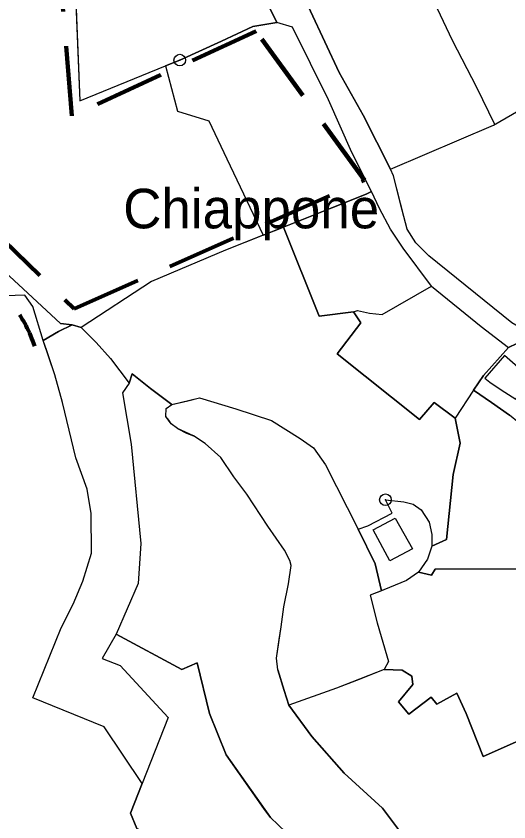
# Model space of a CAD drawing. Extents: x 645880 to 658994, y 884400 to 894744.
# Drawn here: x 657636.1 to 657847.7, y 891569 to 891915 of the extents above; entities that cross this region are included whole.
import ezdxf
from ezdxf.enums import TextEntityAlignment as Align

# ---------------------------------------------------------------- set-up
doc = ezdxf.new("R2010")
doc.units = 0
doc.header["$LTSCALE"] = 10
doc.header["$PDMODE"] = 32
doc.header["$PDSIZE"] = 5
doc.linetypes.add('MEDIUM_DASHED', pattern=[4.5, 3, -1.5])
doc.linetypes.add('SHORT_DASHED', pattern=[2.7, 1.5, -1.2])
for name, color, linetype, lineweight in [('1', 7, 'Continuous', 25), ('13', 7, 'Continuous', 25), ('15', 7, 'MEDIUM_DASHED', 100), ('26', 7, 'Continuous', 25), ('32', 7, 'Continuous', 25), ('41', 7, 'Continuous', 40), ('55', 7, 'Continuous', 25), ('8', 7, 'Continuous', 25), ('9', 7, 'Continuous', 25)]:
    doc.layers.add(name, color=color, linetype=linetype, lineweight=lineweight)
doc.layers.add('60', color=7, linetype='Continuous')

msp = doc.modelspace()

# ---------------------------------------------------------------- linework, layer by layer
at = {"layer": '1'}
for points in [[(657869.29, 891769.47), (657862, 891775.28), (657858.28, 891777.83), (657847.5, 891772.66)], [(657847.5, 891772.66), (657836.84, 891760.76), (657832.51, 891754.43), (657840.28, 891749.06), (657848.05, 891743.69)], [(657782.96, 891694.68), (657787.2, 891696.06), (657797.54, 891701.6), (657794.71, 891707.33)], [(657802.54, 891706.38), (657806.57, 891705.45), (657810.06, 891703.01), (657813.53, 891697.74), (657814.62, 891692.45), (657814.58, 891687.36), (657812.8, 891681.77), (657808.92, 891676.2), (657803.69, 891672.63), (657794.06, 891668.59), (657792.94, 891668.23), (657790.32, 891679.88), (657782.96, 891694.68)]]:
    msp.add_lwpolyline(points, dxfattribs=at)
for points in [[(657867.89, 891752.17), (657853.82, 891762.29), (657845.89, 891769.33), (657837.33, 891759.6), (657839.49, 891757.8), (657844.41, 891754.59), (657850.75, 891750.51), (657853.31, 891753.71), (657863.41, 891746.41)], [(657789.44, 891694.38), (657798.88, 891699.44), (657806.26, 891686.22), (657796.54, 891681.08)]]:
    msp.add_lwpolyline(points, close=True, dxfattribs=at)
msp.add_point((657794.71, 891707.33), dxfattribs=at)
at = {"layer": '13'}
for points in [[(657432.76, 891843.52), (657469.74, 891871.41), (657496.82, 891788.11), (657619.04, 891816.35), (657655.09, 891783.05)], [(657655.09, 891783.05), (657660.19, 891782.51), (657654.33, 891779.66), (657647.73, 891775.77), (657643.28, 891790.37), (657639.86, 891795.15), (657627.13, 891794.74)], [(657709.8, 891749.85), (657714.86, 891751.08), (657730.44, 891746.35), (657745.75, 891741.38)], [(657709.27, 891735.99), (657705.39, 891737.91), (657702.65, 891739.93), (657701.65, 891741.44), (657700.38, 891743.11), (657700.58, 891746.53), (657702.97, 891748.19), (657709.8, 891749.85)], [(657745.75, 891741.38), (657758.07, 891733.66), (657763.76, 891729.58), (657768.91, 891722.35), (657782.96, 891694.68), (657790.32, 891679.88), (657792.94, 891668.23), (657788.18, 891666.42), (657791.15, 891654.44), (657792.82, 891648.53), (657795.99, 891637.83), (657794.21, 891634.37), (657782.32, 891629.77), (657773.68, 891626.41), (657753.26, 891619.18)], [(657749.11, 891647.27), (657749.93, 891652.71), (657751.03, 891661.3), (657753.09, 891671.25), (657754.23, 891679.11), (657753.65, 891681.17), (657751.36, 891685.75), (657744.12, 891696.02), (657735.2, 891709.72), (657729.59, 891717.12), (657724.05, 891725.43), (657717.28, 891731.51), (657712.28, 891734.73), (657709.27, 891735.99)], [(657678.98, 891649.67), (657673.01, 891639.13), (657680.69, 891636.19), (657701.38, 891613.82), (657690.25, 891585.42)], [(657678.98, 891649.67), (657673.01, 891639.13), (657680.69, 891636.19), (657701.38, 891613.82), (657690.25, 891585.42), (657685.19, 891572.75), (657687.9, 891566.1), (657729.26, 891544.2), (657738.1, 891535.49)], [(657713.85, 891637.29), (657707.19, 891634.42), (657678.98, 891649.67)], [(657753.26, 891619.18), (657751.27, 891625.38), (657748.45, 891634.33), (657747.88, 891639.32), (657749.11, 891647.27)], [(657782.7, 891539.42), (657765.1, 891551.91), (657745.3, 891570.84), (657742.5, 891574.78), (657726.25, 891597.71), (657719.17, 891615.54), (657713.85, 891637.29)]]:
    msp.add_lwpolyline(points, dxfattribs=at)
at = {"layer": '15'}
msp.add_lwpolyline([(657323.77, 891717.8), (657394.25, 891834.07), (657474.26, 891879.81), (657500.92, 891799.76), (657624.74, 891824.54), (657660.93, 891789.28), (657785.69, 891844.55), (657739.13, 891908.57), (657659.98, 891872.19), (657653.31, 891953.19)], dxfattribs=at)
at = {"layer": '26'}
msp.add_line((657796.81, 891849.31), (657841.15, 891868.23), dxfattribs=at)
for points in [[(657758.69, 892137.73), (657757.11, 892135.65), (657749.33, 892122.75), (657744.59, 892112.88), (657742.31, 892105.2), (657741.36, 892090.31), (657742.18, 892050.76), (657743.37, 891989.94), (657744.93, 891965.34), (657750.21, 891944.26), (657762.46, 891917.16), (657774.87, 891890.81), (657785.16, 891872.46), (657796.81, 891849.31)], [(657841.15, 891868.23), (657881.18, 891891.34), (657903.67, 891854.63), (657911.35, 891843.44), (657994.66, 891890.15), (657997.88, 891892.48)]]:
    msp.add_lwpolyline(points, dxfattribs=at)
at = {"layer": '32'}
for points in [[(657660.06, 891962.27), (657663.45, 891878.6), (657700.24, 891893.63)], [(657742.24, 891820.98), (657726, 891814.54), (657694.16, 891801), (657664.05, 891781.35), (657660.19, 891782.51), (657655.09, 891783.05), (657619.04, 891816.35), (657496.82, 891788.11), (657496.82, 891788.11), (657469.74, 891871.41), (657432.76, 891843.52), (657429.08, 891844.98), (657422.3, 891845.12), (657414.96, 891840.81), (657410.91, 891832.97), (657412.56, 891823.6), (657398.01, 891831.07), (657351.25, 891848.9), (657334.55, 891854.45), (657336.53, 891898.64), (657333.31, 891925.98)], [(657748.04, 891912.29), (657737.78, 891910.62), (657724.24, 891904.23), (657706.38, 891896.14), (657700.24, 891893.63)], [(657788.68, 891839.73), (657780.33, 891856.49), (657770.21, 891879.15), (657754.85, 891910.24), (657748.04, 891912.29)], [(657700.24, 891893.63), (657705.45, 891874.29), (657718.91, 891870), (657726.64, 891853.82)], [(657700.24, 891893.63), (657705.45, 891874.29), (657718.91, 891870), (657726.64, 891853.82), (657742.24, 891820.98)], [(657848.94, 891783.31), (657813.3, 891812.14), (657807.8, 891817.64), (657804.01, 891823.52), (657801.92, 891831.68), (657798.13, 891846.47), (657796.81, 891849.31), (657841.15, 891868.23), (657881.18, 891891.34)], [(657726.64, 891853.82), (657742.24, 891820.98), (657786.43, 891838.51), (657788.68, 891839.73)]]:
    msp.add_lwpolyline(points, dxfattribs=at)
at = {"layer": '41', "linetype": 'SHORT_DASHED', "lineweight": 80}
msp.add_arc((657590.77, 891756.16), 55.95, 17.7593, 57.1028, dxfattribs=at)
at = {"layer": '55'}
for points in [[(657841.64, 891868.51), (657833.93, 891884.34), (657823.46, 891904.64), (657804.01, 891945.77), (657799.28, 891957.09), (657796.41, 891967.76), (657795.72, 891971.23), (657794.89, 891982.35), (657792.85, 892070.98), (657792.65, 892093.07), (657794.14, 892096.06), (657804.02, 892113.46), (657812.57, 892128.28), (657814.84, 892148), (657816.57, 892152.85), (657808.89, 892139.52)], [(657735.78, 892010.9), (657735.34, 891976.8), (657736.37, 891963.27), (657738.03, 891948.21), (657743.89, 891923.77), (657745.11, 891918.4), (657748.04, 891912.29)], [(657744.93, 891965.34), (657750.21, 891944.26), (657762.46, 891917.16), (657774.87, 891890.81), (657785.16, 891872.46), (657796.81, 891849.31), (657841.15, 891868.23), (657841.64, 891868.51)], [(657796.81, 891849.31), (657785.16, 891872.46), (657774.87, 891890.81), (657762.46, 891917.16), (657750.21, 891944.26), (657744.93, 891965.34)], [(657748.04, 891912.29), (657737.78, 891910.62), (657724.24, 891904.23), (657706.38, 891896.14), (657700.24, 891893.63)], [(657700.24, 891893.63), (657705.45, 891874.29), (657718.91, 891870), (657726.64, 891853.82), (657742.24, 891820.98), (657750.85, 891824.4), (657766.25, 891786.18), (657781.02, 891788.05), (657784.13, 891783.26), (657773.99, 891769.98), (657809.36, 891741.8), (657815.59, 891749.14), (657824.59, 891742.44), (657826.73, 891731.58), (657823.82, 891718.16), (657820.92, 891690.19), (657814.58, 891687.36), (657812.8, 891681.77), (657808.92, 891676.2), (657803.69, 891672.63), (657794.06, 891668.59), (657788.18, 891666.42), (657791.15, 891654.44), (657792.82, 891648.53), (657795.99, 891637.83), (657794.21, 891634.37), (657773.68, 891626.41), (657753.26, 891619.18), (657763.03, 891605.7), (657777.02, 891589.95), (657793.46, 891574.89), (657807.15, 891556.57)], [(657832.51, 891754.43), (657836.84, 891760.76), (657847.5, 891772.66), (657858.28, 891777.83), (657848.94, 891783.31), (657813.3, 891812.14), (657807.8, 891817.64), (657804.01, 891823.52), (657798.13, 891846.47), (657796.81, 891849.31)], [(657859.76, 891733.14), (657855.89, 891736.52), (657851.89, 891740.44), (657848.05, 891743.69), (657840.28, 891749.06), (657832.51, 891754.43)]]:
    msp.add_lwpolyline(points, dxfattribs=at)
at = {"layer": '8'}
msp.add_line((657706.38, 891896.14), (657724.24, 891904.23), dxfattribs=at)
for points in [[(657736.37, 891963.27), (657723.99, 891959.82), (657704.2, 891955.52), (657679.94, 891949.67), (657667.55, 891947.95), (657660.68, 891946.99), (657663.45, 891878.6)], [(657748.04, 891912.29), (657745.11, 891918.4), (657743.89, 891923.77), (657738.03, 891948.21), (657736.37, 891963.27)], [(657724.24, 891904.23), (657737.78, 891910.62), (657748.04, 891912.29)], [(657663.45, 891878.6), (657700.24, 891893.63), (657706.38, 891896.14)], [(657781.02, 891788.05), (657782.65, 891788.55), (657787.88, 891787.41), (657793.25, 891786.87), (657814.44, 891799.12), (657802.35, 891815.38), (657796.87, 891823.5), (657792.15, 891832.39), (657788.68, 891839.73), (657786.43, 891838.51), (657750.85, 891824.4)], [(657750.85, 891824.4), (657726, 891814.54), (657694.16, 891801), (657664.05, 891781.35), (657670.38, 891774.88), (657676.65, 891768.05), (657684.63, 891757.38), (657685.98, 891761.42), (657693.74, 891755.08), (657702.97, 891748.19), (657714.86, 891751.08), (657730.44, 891746.35), (657745.75, 891741.38), (657758.07, 891733.66), (657763.76, 891729.58), (657768.91, 891722.35), (657782.96, 891694.68), (657787.2, 891696.06), (657797.54, 891701.6), (657794.71, 891707.33), (657802.54, 891706.38), (657806.57, 891705.45), (657810.06, 891703.01), (657813.53, 891697.74)], [(657750.85, 891824.4), (657766.25, 891786.18), (657781.02, 891788.05)], [(657781.02, 891788.05), (657766.25, 891786.18), (657750.85, 891824.4)], [(657652.64, 891760.91), (657647.73, 891775.77), (657643.28, 891790.37), (657639.86, 891795.15), (657627.13, 891794.74)], [(657824.59, 891742.44), (657815.59, 891749.14), (657809.36, 891741.8), (657773.99, 891769.98), (657784.13, 891783.26), (657781.02, 891788.05)], [(657664.76, 891672.32), (657668.49, 891684.45), (657668.36, 891701.4), (657666.65, 891711.82), (657661.77, 891725.35), (657656.05, 891749.04), (657652.64, 891760.91), (657649.27, 891771.3), (657647.73, 891775.77), (657654.33, 891779.66), (657660.19, 891782.51), (657664.05, 891781.35)], [(657664.05, 891781.35), (657670.38, 891774.88), (657676.65, 891768.05), (657684.63, 891757.38), (657681.69, 891753.19)], [(657685.98, 891761.42), (657684.63, 891757.38), (657681.69, 891753.19), (657685.45, 891731.19)], [(657700.38, 891743.11), (657700.58, 891746.53), (657702.97, 891748.19), (657693.74, 891755.08), (657685.98, 891761.42)], [(657661.77, 891725.35), (657656.05, 891749.04), (657652.64, 891760.91)], [(657859.76, 891733.14), (657855.89, 891736.52), (657851.89, 891740.44), (657848.05, 891743.69), (657840.28, 891749.06), (657832.51, 891754.43), (657824.59, 891742.44)], [(657681.69, 891753.19), (657685.45, 891731.19), (657689.68, 891688.51), (657689.68, 891688.51), (657689.68, 891688.5), (657689.69, 891688.5), (657688.53, 891671.33), (657678.98, 891649.67)], [(657709.27, 891735.99), (657705.39, 891737.91), (657702.65, 891739.93), (657700.38, 891743.11)], [(657824.59, 891742.44), (657826.73, 891731.58), (657823.82, 891718.16), (657820.92, 891690.19), (657814.58, 891687.36)], [(657814.58, 891687.36), (657820.92, 891690.19), (657823.82, 891718.16), (657826.73, 891731.58), (657824.59, 891742.44)], [(657749.93, 891652.71), (657751.03, 891661.3), (657753.09, 891671.25), (657754.23, 891679.11), (657753.65, 891681.17), (657751.36, 891685.75), (657744.12, 891696.02), (657735.2, 891709.72), (657729.59, 891717.12), (657724.05, 891725.43), (657717.28, 891731.51), (657712.28, 891734.73), (657709.27, 891735.99)], [(657685.45, 891731.19), (657689.68, 891688.51), (657688.53, 891671.33), (657678.98, 891649.67), (657707.19, 891634.42), (657713.85, 891637.29), (657719.17, 891615.54), (657726.25, 891597.71), (657745.3, 891570.84)], [(657668.49, 891684.45), (657668.36, 891701.4), (657666.65, 891711.82), (657661.77, 891725.35)], [(657813.53, 891697.74), (657814.62, 891692.45), (657814.58, 891687.36)], [(657814.58, 891687.36), (657812.8, 891681.77), (657808.92, 891676.2), (657814.53, 891674.87), (657815.99, 891677.45), (657871.29, 891677.65)], [(657673.84, 891609.79), (657643.18, 891622.22), (657655.44, 891652.26), (657660.56, 891662.52), (657664.76, 891672.32), (657668.49, 891684.45)], [(657871.29, 891677.65), (657815.99, 891677.45), (657814.53, 891674.87), (657808.92, 891676.2), (657803.69, 891672.63)], [(657655.44, 891652.26), (657660.57, 891662.52), (657664.76, 891672.32)], [(657803.69, 891672.63), (657794.06, 891668.59), (657792.94, 891668.23), (657788.18, 891666.42), (657791.15, 891654.44), (657792.82, 891648.53), (657795.99, 891637.83), (657794.21, 891634.37), (657801.87, 891634.21), (657806.05, 891631.57), (657806.49, 891628.05), (657800.33, 891620.57), (657804.73, 891615.29), (657814.4, 891622.55)], [(657678.98, 891649.67), (657673.01, 891639.13), (657680.69, 891636.19), (657701.38, 891613.82), (657690.25, 891585.42), (657673.84, 891609.79), (657643.18, 891622.22), (657655.44, 891652.26)], [(657753.26, 891619.18), (657751.27, 891625.38), (657748.45, 891634.33), (657747.88, 891639.32), (657749.93, 891652.71)], [(657829.35, 891615.51), (657825.39, 891624.31), (657816.82, 891619.47), (657814.4, 891622.55), (657804.73, 891615.29), (657800.33, 891620.57), (657806.49, 891628.05), (657806.05, 891631.57), (657801.87, 891634.21), (657794.21, 891634.37), (657773.68, 891626.41), (657753.26, 891619.18), (657748.45, 891634.33)], [(657748.45, 891634.33), (657751.27, 891625.38), (657753.26, 891619.18)], [(657814.4, 891622.55), (657816.82, 891619.47), (657825.39, 891624.31), (657829.35, 891615.51), (657836.61, 891597.04), (657853.09, 891604.3), (657873.32, 891611.56), (657862.24, 891635.8), (657892.62, 891627.9), (657892.41, 891634.92)], [(657753.26, 891619.18), (657763.03, 891605.7), (657777.02, 891589.95), (657793.46, 891574.89), (657807.15, 891556.57), (657814.45, 891545.21), (657819.95, 891519.54), (657827.28, 891493.86), (657829.12, 891478.74), (657834.61, 891463.61), (657796.59, 891460.4), (657792, 891421.89), (657773.22, 891357.71), (657767.03, 891348.96)], [(657767.03, 891348.96), (657773.22, 891357.71), (657792, 891421.89), (657796.59, 891460.4), (657834.61, 891463.61), (657829.12, 891478.74), (657827.28, 891493.86), (657819.95, 891519.54), (657814.45, 891545.21), (657807.15, 891556.57), (657793.46, 891574.89), (657777.02, 891589.95), (657763.03, 891605.7), (657753.26, 891619.18)], [(657878.61, 891597.51), (657874.56, 891608.75), (657873.32, 891611.56), (657853.09, 891604.3), (657836.61, 891597.04), (657829.35, 891615.51)], [(657747.59, 891520.62), (657738.1, 891535.48), (657729.26, 891544.2), (657687.9, 891566.1), (657685.19, 891572.75), (657690.25, 891585.42), (657673.84, 891609.79)], [(657745.3, 891570.84), (657765.1, 891551.91), (657782.7, 891539.42)]]:
    msp.add_lwpolyline(points, dxfattribs=at)
msp.add_lwpolyline([(657705.39, 891737.91), (657709.27, 891735.99), (657712.28, 891734.73)], close=True, dxfattribs=at)
msp.add_point((657706.38, 891896.14), dxfattribs=at)
at = {"layer": '9'}
for points in [[(657809.36, 891741.8), (657773.99, 891769.98), (657784.13, 891783.26), (657781.02, 891788.05), (657782.65, 891788.55), (657787.88, 891787.41), (657793.25, 891786.87), (657814.44, 891799.12)], [(657814.44, 891799.12), (657835.79, 891781.73), (657847.5, 891772.66)], [(657847.5, 891772.66), (657836.84, 891760.76), (657832.51, 891754.43), (657824.59, 891742.44), (657815.59, 891749.14), (657809.36, 891741.8)]]:
    msp.add_lwpolyline(points, dxfattribs=at)

# ---------------------------------------------------------------- texts
at = {"layer": '60'}
msp.add_text('Chiappone', height=17, dxfattribs=at).set_placement((657737.04, 891823.9), align=Align.CENTER)

doc.saveas('drawing.dxf')
